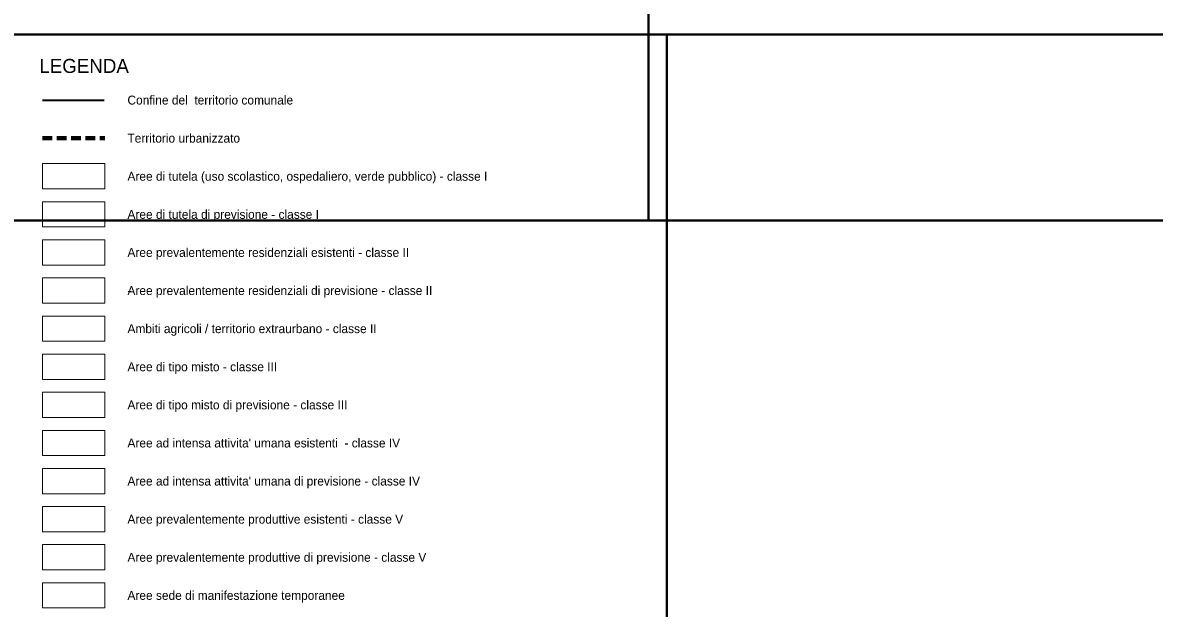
# Model space of a CAD drawing. Extents: x 645880 to 658994, y 884400 to 894744.
# Drawn here: x 648057 to 651612, y 887787 to 889625 of the extents above; entities that cross this region are included whole.
import ezdxf

# ---------------------------------------------------------------- set-up
doc = ezdxf.new("R2010")
doc.units = 0
doc.header["$LTSCALE"] = 10
doc.linetypes.add('MEDIUM_DASHED', pattern=[4.5, 3, -1.5])
doc.layers.add('62', color=7, linetype='Continuous', lineweight=35)
doc.layers.add('63', color=7, linetype='Continuous', lineweight=35)

msp = doc.modelspace()

# ---------------------------------------------------------------- linework, layer by layer
at = {"layer": '62', "lineweight": 40}
for points in [[(650022.35, 889003.81), (658994.16, 889003.81), (658994.16, 894743.81), (650022.35, 894743.81)], [(650022.35, 889003.81), (658994.16, 889003.81), (658994.16, 894743.81), (650022.35, 894743.81)], [(647922.35, 889003.81), (650022.35, 889003.81), (650022.35, 891773.81), (647922.35, 891773.81)]]:
    msp.add_lwpolyline(points, close=True, dxfattribs=at)
at = {"layer": '63'}
msp.add_line((648119.66, 889382.32), (648313.62, 889382.32), dxfattribs=at)
at = {"layer": '63', "linetype": 'MEDIUM_DASHED', "lineweight": 80}
msp.add_line((648119.66, 889262.7), (648314.98, 889262.7), dxfattribs=at)
at = {"layer": '63', "lineweight": 40}
for points in [[(647980.32, 884399.72), (650080.32, 884399.72), (650080.32, 889588.16), (647980.32, 889588.16)], [(656397.82, 884399.72), (650080.32, 884399.72), (650080.32, 889588.16), (656397.82, 889588.16)]]:
    msp.add_lwpolyline(points, close=True, dxfattribs=at)
at = {"layer": '63', "lineweight": 13}
for points in [[(648119.66, 889182.7), (648315.5, 889182.7), (648315.5, 889103.5), (648119.66, 889103.5)], [(648119.66, 889063.1), (648315.5, 889063.1), (648315.5, 888983.9), (648119.66, 888983.9)], [(648119.66, 888943.54), (648315.5, 888943.54), (648315.5, 888864.34), (648119.66, 888864.34)], [(648119.66, 888823.94), (648315.5, 888823.94), (648315.5, 888744.74), (648119.66, 888744.74)], [(648119.66, 888704.4), (648315.5, 888704.4), (648315.5, 888625.2), (648119.66, 888625.2)], [(648119.66, 888584.74), (648315.5, 888584.74), (648315.5, 888505.54), (648119.66, 888505.54)], [(648119.66, 888465.14), (648315.5, 888465.14), (648315.5, 888385.94), (648119.66, 888385.94)], [(648119.66, 888345.54), (648315.5, 888345.54), (648315.5, 888266.34), (648119.66, 888266.34)], [(648119.66, 888225.94), (648315.5, 888225.94), (648315.5, 888146.74), (648119.66, 888146.74)], [(648119.66, 888106.34), (648315.5, 888106.34), (648315.5, 888027.14), (648119.66, 888027.14)], [(648119.66, 887986.74), (648315.5, 887986.74), (648315.5, 887907.54), (648119.66, 887907.54)], [(648119.66, 887867.2), (648315.5, 887867.2), (648315.5, 887788), (648119.66, 887788)]]:
    msp.add_lwpolyline(points, close=True, dxfattribs=at)

# ---------------------------------------------------------------- texts
at = {"layer": '63'}
for s, height, p in [('LEGENDA', 44, (648109.78, 889467.37)), ('Confine del  territorio comunale  ', 28, (648386.48, 889368.23)), ('Territorio urbanizzato', 28, (648386.48, 889248.67)), ('Aree di tutela (uso scolastico, ospedaliero, verde pubblico) - classe I', 28, (648386.48, 889129.03)), ('Aree di tutela di previsione - classe I', 28, (648386.48, 889009.43)), ('Aree prevalentemente residenziali esistenti - classe II', 28, (648386.48, 888889.87)), ('Aree prevalentemente residenziali di previsione - classe II', 28, (648386.48, 888770.27)), ('-', 28.12, (648386.48, 888770.21)), ('Ambiti agricoli / territorio extraurbano - classe II', 28, (648386.48, 888650.73)), ('Aree di tipo misto - classe III', 28, (648386.48, 888531.07)), ('Aree di tipo misto di previsione - classe III', 28, (648386.48, 888411.47)), ("Aree ad intensa attivita' umana esistenti  - classe IV", 28, (648386.48, 888291.87)), ("Aree ad intensa attivita' umana di previsione - classe IV", 28, (648386.48, 888172.27)), ('Aree prevalentemente produttive esistenti - classe V', 28, (648386.48, 888052.67)), ('Aree prevalentemente produttive di previsione - classe V', 28, (648386.48, 887933.07)), ('Aree sede di manifestazione temporanee', 28, (648386.48, 887813.53))]:
    msp.add_text(s, height=height, dxfattribs=at).set_placement(p)

doc.saveas('drawing.dxf')
